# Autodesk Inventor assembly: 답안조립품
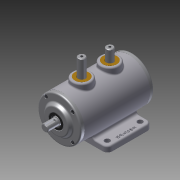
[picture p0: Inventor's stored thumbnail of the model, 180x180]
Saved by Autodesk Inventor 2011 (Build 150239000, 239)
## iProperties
Created: 2014-12
Part Number: 답안조립품
Document SubType Name: Assembly
Designer: user
Author: user
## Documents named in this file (10)
- E:\441225V1015\답안조립품.iam
- E:\441225V1015\1-본체.ipt
- E:\441225V1015\4-축.ipt
- E:\441225V1015\베어링 6203.ipt
- E:\441225V1015\뒷커버.ipt
- E:\441225V1015\M4-소켓머리.ipt
- E:\441225V1015\부시.ipt
- E:\441225V1015\슬라이더.ipt
- E:\441225V1015\앞커버.ipt
- E:\441225V1015\오일실.ipt
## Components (13 placed, 5 different names)
1. 1-본체:1
2. 4-축:1
3. 7-베어링 6203:1
4. 7-베어링 6203:2
5. 8-오일실:1
6. 9-M4-소켓머리:1
7. 9-M4-소켓머리:2
8. 9-M4-소켓머리:3
9. 9-M4-소켓머리:4
10. 9-M4-소켓머리:5
11. 9-M4-소켓머리:6
12. 9-M4-소켓머리:7
13. 9-M4-소켓머리:8
